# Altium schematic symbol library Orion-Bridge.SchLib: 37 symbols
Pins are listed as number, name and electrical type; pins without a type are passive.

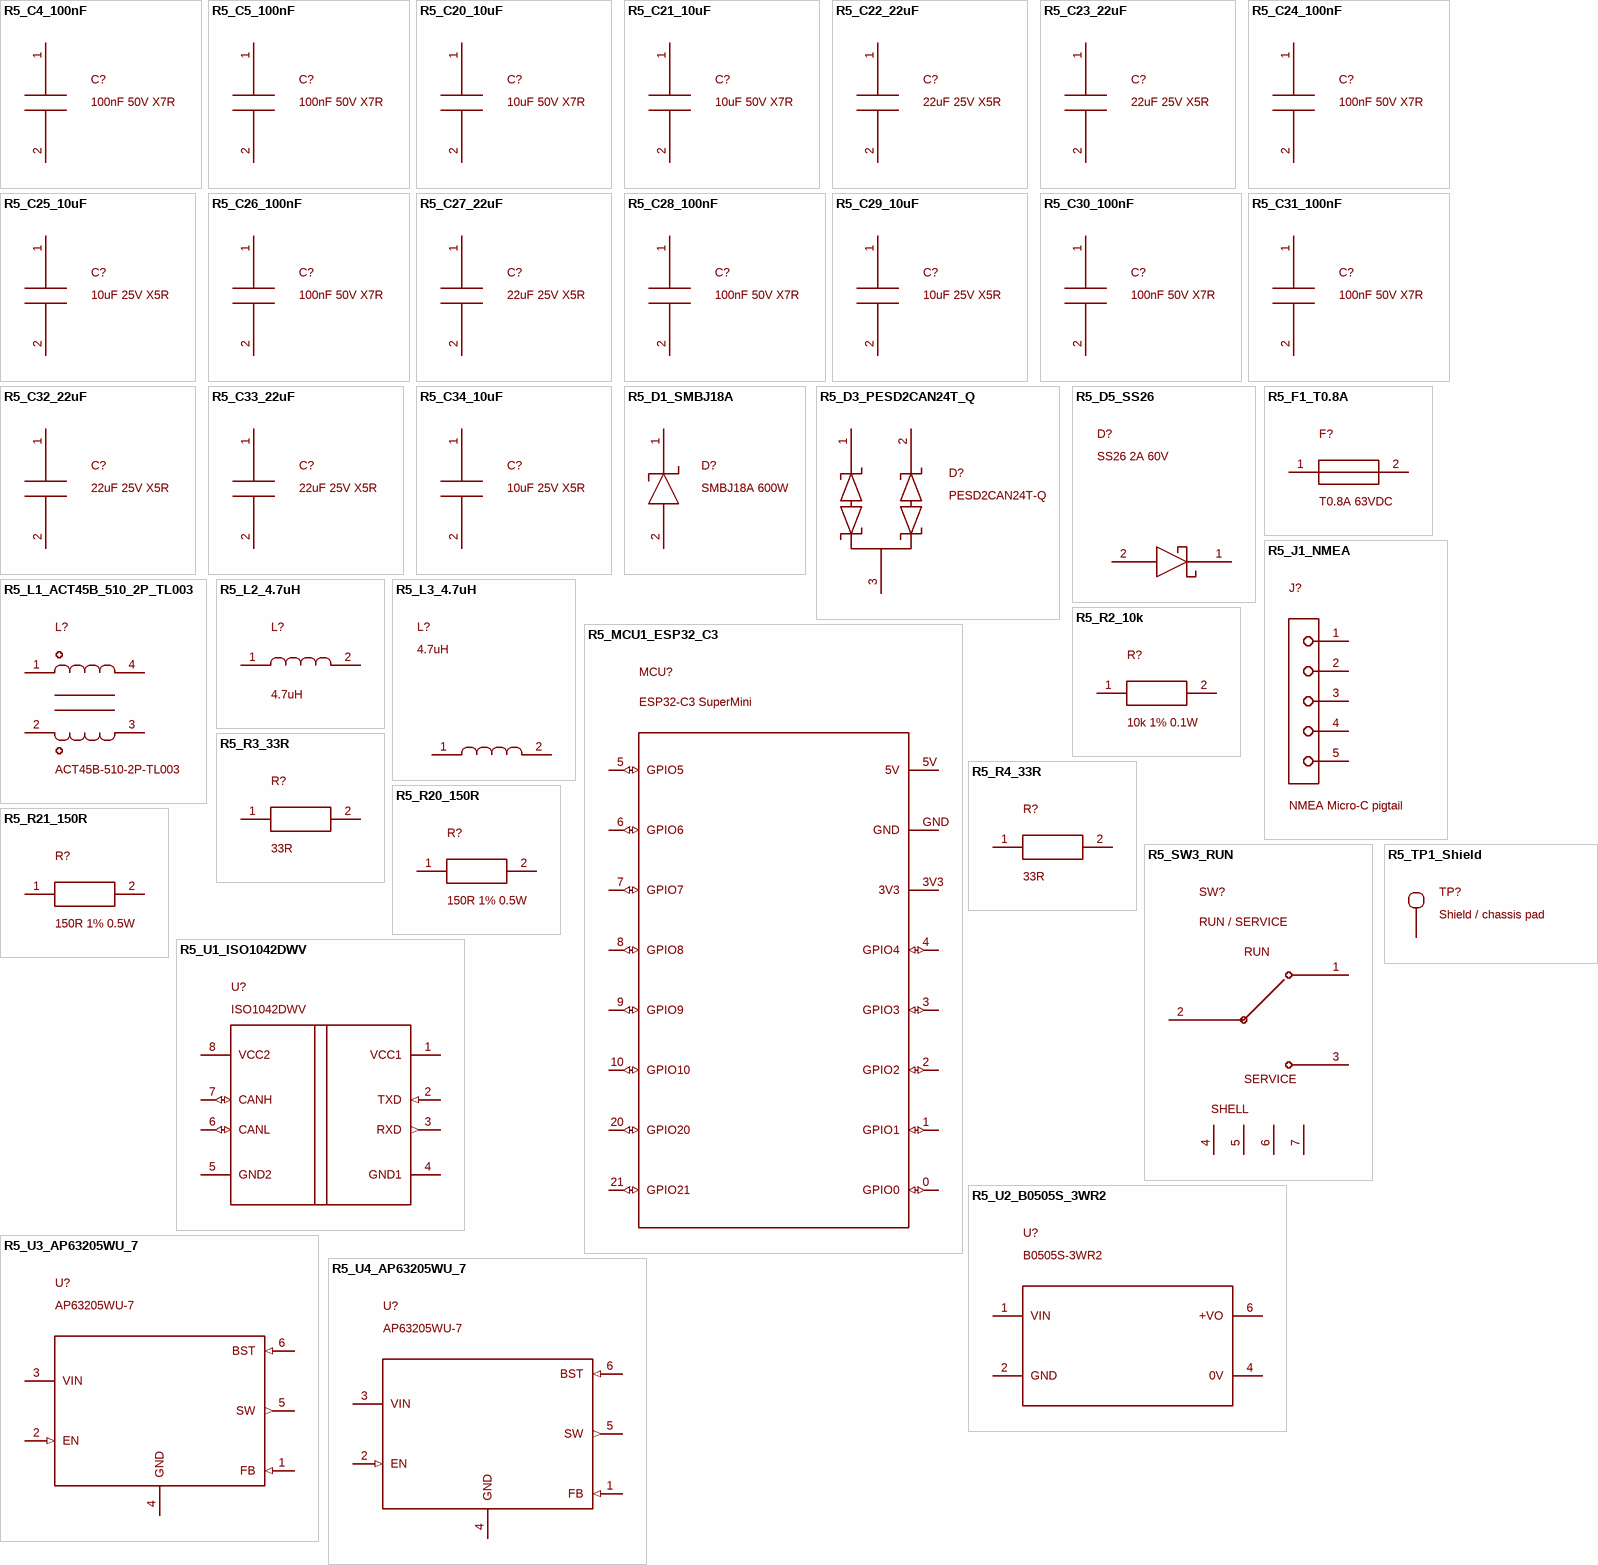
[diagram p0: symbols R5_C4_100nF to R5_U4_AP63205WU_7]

## R5_C4_100nF
designator C?, comment 100nF 50V X7R
100nF 16V X7R - generic specification; manufacturer/MPN not selected; Manufacturer: YAGEO; MPN: CC0603KRX7R9BB104
footprint C0603
pins: 1, 2

## R5_C5_100nF
designator C?, comment 100nF 50V X7R
100nF 16V X7R - generic specification; manufacturer/MPN not selected; Manufacturer: YAGEO; MPN: CC0603KRX7R9BB104
footprint C0603
pins: 1, 2

## R5_C20_10uF
designator C?, comment 10uF 50V X7R
Manufacturer: Samsung Electro-Mechanics; MPN: CL32B106KBJNNNE
footprint C1210
pins: 1, 2

## R5_C21_10uF
designator C?, comment 10uF 50V X7R
Manufacturer: Samsung Electro-Mechanics; MPN: CL32B106KBJNNNE
footprint C1210
pins: 1, 2

## R5_C22_22uF
designator C?, comment 22uF 25V X5R
Manufacturer: Samsung Electro-Mechanics; MPN: CL31A226KAHNNNE
footprint C1206
pins: 1, 2

## R5_C23_22uF
designator C?, comment 22uF 25V X5R
Manufacturer: Samsung Electro-Mechanics; MPN: CL31A226KAHNNNE
footprint C1206
pins: 1, 2

## R5_C24_100nF
designator C?, comment 100nF 50V X7R
Manufacturer: YAGEO; MPN: CC0603KRX7R9BB104
footprint C0603
pins: 1, 2

## R5_C25_10uF
designator C?, comment 10uF 25V X5R
Manufacturer: Samsung Electro-Mechanics; MPN: CL21A106KAYNNNE
footprint C0805
pins: 1, 2

## R5_C26_100nF
designator C?, comment 100nF 50V X7R
Manufacturer: YAGEO; MPN: CC0603KRX7R9BB104
footprint C0603
pins: 1, 2

## R5_C27_22uF
designator C?, comment 22uF 25V X5R
Manufacturer: Samsung Electro-Mechanics; MPN: CL31A226KAHNNNE
footprint C1206
pins: 1, 2

## R5_C28_100nF
designator C?, comment 100nF 50V X7R
Manufacturer: YAGEO; MPN: CC0603KRX7R9BB104
footprint C0603
pins: 1, 2

## R5_C29_10uF
designator C?, comment 10uF 25V X5R
Manufacturer: Samsung Electro-Mechanics; MPN: CL21A106KAYNNNE
footprint C0805
pins: 1, 2

## R5_C30_100nF
designator C?, comment 100nF 50V X7R
Manufacturer: YAGEO; MPN: CC0603KRX7R9BB104
footprint C0603
pins: 1, 2

## R5_C31_100nF
designator C?, comment 100nF 50V X7R
Manufacturer: YAGEO; MPN: CC0603KRX7R9BB104
footprint C0603
pins: 1, 2

## R5_C32_22uF
designator C?, comment 22uF 25V X5R
Manufacturer: Samsung Electro-Mechanics; MPN: CL31A226KAHNNNE
footprint C1206
pins: 1, 2

## R5_C33_22uF
designator C?, comment 22uF 25V X5R
Manufacturer: Samsung Electro-Mechanics; MPN: CL31A226KAHNNNE
footprint C1206
pins: 1, 2

## R5_C34_10uF
designator C?, comment 10uF 25V X5R
10uF local module5V reservoir after RUN/SERVICE switch; Manufacturer: Samsung Electro-Mechanics; MPN: CL21A106KAYNNNE
footprint C0805
pins: 1, 2

## R5_D1_SMBJ18A
designator D?, comment SMBJ18A 600W
Manufacturer: BORN
footprint SMB
pins: 1 K, 2 A

## R5_D3_PESD2CAN24T_Q
designator D?, comment PESD2CAN24T-Q
Manufacturer: Nexperia; MPN: PESD2CAN24T-QR
footprint SOT23_NEXPERIA_REFLOW
pins: 1 K1, 2 K2, 3 CC

## R5_D5_SS26
designator D?, comment SS26 2A 60V
Manufacturer: MDD(Microdiode Semiconductor)
footprint SMA
pins: 1 K, 2 A

## R5_F1_T0.8A
designator F?, comment T0.8A 63VDC
0.8 A slow-blow SMD ceramic fuse, 63 VDC, 50 A interrupt rating; Manufacturer: BOURNS; MPN: SF-1206S080-2
footprint BOURNS_SF1206S
pins: 1, 2

## R5_J1_NMEA
designator J?, comment NMEA Micro-C pigtail
Five direct wire-solder pads for a separately selected Micro-C cable; this is a PCB interface, not an invented connector MPN or face view
footprint PIGTAIL_5_P3_D1P3
pins: 1 SHIELD, 2 NET-S, 3 NET-C, 4 CAN-H, 5 CAN-L

## R5_L1_ACT45B_510_2P_TL003
designator L?, comment ACT45B-510-2P-TL003
Manufacturer: TDK
footprint ACT45B
pins: 1 H_EXT, 2 L_EXT, 3 L_IC, 4 H_IC

## R5_L2_4.7uH
designator L?, comment 4.7uH
Manufacturer: Sunlord; MPN: SWPA4030S4R7MT
footprint SUNLORD_SWPA4030
pins: 1, 2

## R5_L3_4.7uH
designator L?, comment 4.7uH
Manufacturer: Sunlord; MPN: SWPA4030S4R7MT
footprint SUNLORD_SWPA4030
pins: 1, 2

## R5_MCU1_ESP32_C3
designator MCU?, comment ESP32-C3 SuperMini
User-selected C3 SuperMini; original onboard USB/BOOT/RESET; direct castellated solder mounting; Manufacturer: Meshnology (seller brand; OEM undisclosed); MPN: ESP32-C3 SuperMini / ASIN B0FN4F6244
footprint SUPERC3_B0FN4F6244_CAST16_SMD
pins: 0 GPIO0 (io), 1 GPIO1 (io), 2 GPIO2 (io), 3 GPIO3 (io), 3V3 (power), 4 GPIO4 (io), 5 GPIO5 (io), 5V (power), 6 GPIO6 (io), 7 GPIO7 (io), 8 GPIO8 (io), 9 GPIO9 (io), 10 GPIO10 (io), 20 GPIO20 (io), 21 GPIO21 (io), GND (power)

## R5_R2_10k
designator R?, comment 10k 1% 0.1W
10k - generic specification; manufacturer/MPN not selected; Manufacturer: UNI-ROYAL(Uniroyal Elec); MPN: 0603WAF1002T5E
footprint R0603
pins: 1, 2

## R5_R3_33R
designator R?, comment 33R
33R - generic specification; manufacturer/MPN not selected; Manufacturer: UNI-ROYAL(Uniroyal Elec); MPN: 0603WAF330JT5E
footprint R0603
pins: 1, 2

## R5_R4_33R
designator R?, comment 33R
33R - generic specification; manufacturer/MPN not selected; Manufacturer: UNI-ROYAL(Uniroyal Elec); MPN: 0603WAF330JT5E
footprint R0603
pins: 1, 2

## R5_R20_150R
designator R?, comment 150R 1% 0.5W
Manufacturer: SEI(Stackpole Elec); MPN: RNCP1206FTD150R
footprint R1206
pins: 1, 2

## R5_R21_150R
designator R?, comment 150R 1% 0.5W
Manufacturer: SEI(Stackpole Elec); MPN: RNCP1206FTD150R
footprint R1206
pins: 1, 2

## R5_SW3_RUN
designator SW?, comment RUN / SERVICE
Side-actuated SPDT service supply disconnect, 1A at6V, original SuperMini USB service; Manufacturer: G-Switch; MPN: MK-12C02-G020
footprint GSWITCH_MK12C02_G020
pins: 1 RUN_IN, 2 COMMON, 3 SERVICE_NC, 4 SHIELD1, 5 SHIELD2, 6 SHIELD3, 7 SHIELD4

## R5_TP1_Shield
designator TP?, comment Shield / chassis pad
Shield / chassis pad - generic specification; manufacturer/MPN not selected
footprint TESTPOINT_2MM
pins: 1 SHIELD

## R5_U1_ISO1042DWV
designator U?, comment ISO1042DWV
Manufacturer: Texas Instruments; MPN: ISO1042DWVR
footprint SOIC8_DWV
pins: 1 VCC1 (power), 2 TXD (in), 3 RXD (out), 4 GND1 (power), 5 GND2 (power), 6 CANL (io), 7 CANH (io), 8 VCC2 (power)

## R5_U2_B0505S_3WR2
designator U?, comment B0505S-3WR2
Manufacturer: EVISUN
footprint EVISUN_B0505S_3WR2
pins: 1 VIN (power), 2 GND (power), 4 0V (power), 6 +VO (power)

## R5_U3_AP63205WU_7
designator U?, comment AP63205WU-7
Manufacturer: Diodes Incorporated
footprint TSOT26_DIODES
pins: 1 FB (in), 2 EN (in), 3 VIN (power), 4 GND (power), 5 SW (out), 6 BST (in)

## R5_U4_AP63205WU_7
designator U?, comment AP63205WU-7
Isolated-side 5V buck / high-duty pass-through, feeding physical RUN/SERVICE disconnect; Manufacturer: Diodes Incorporated
footprint TSOT26_DIODES
pins: 1 FB (in), 2 EN (in), 3 VIN (power), 4 GND (power), 5 SW (out), 6 BST (in)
